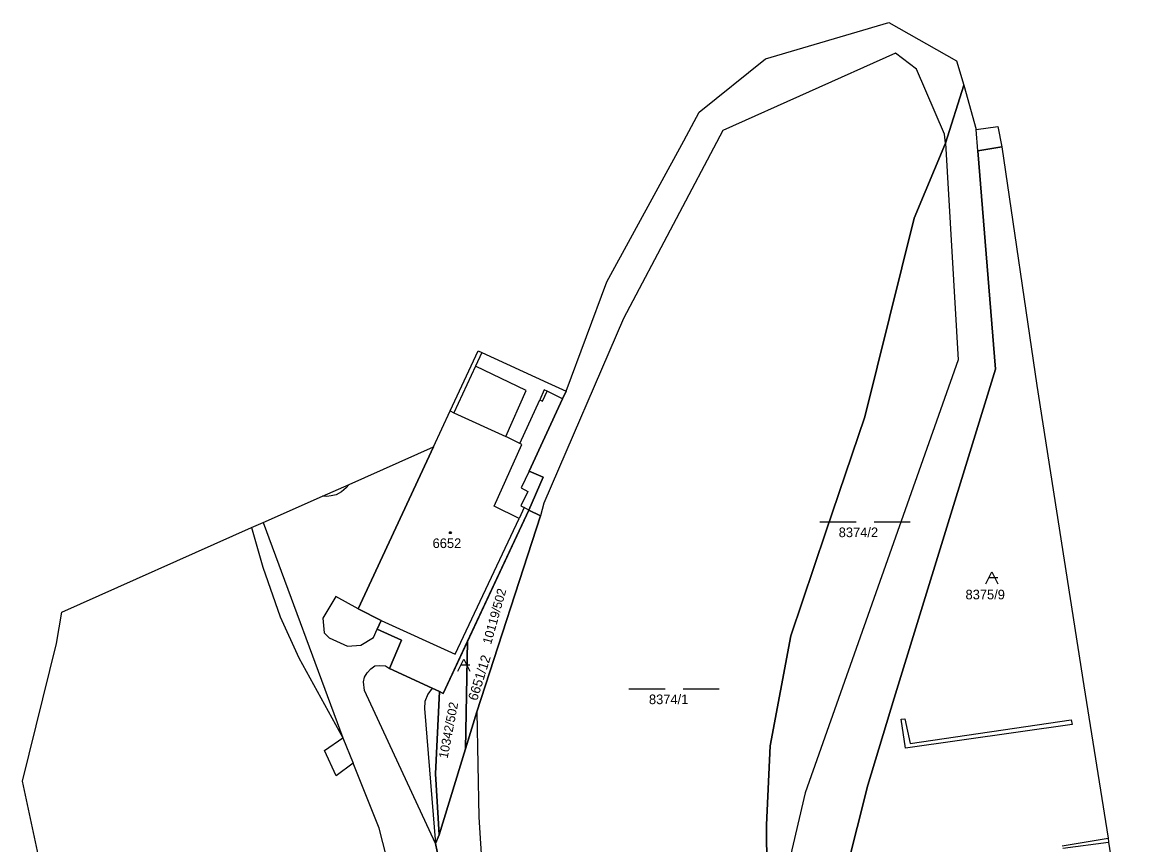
# Model space of a CAD drawing. Extents: x -263587 to -261993, y -1238795 to -1236748.
# Drawn here: x -262974.5 to -262788.7, y -1236884.7 to -1236748.1 of the extents above; entities that cross this region are included whole.
import ezdxf

# ---------------------------------------------------------------- set-up
doc = ezdxf.new("R2010")
doc.units = 0
doc.layers.add('Vrstva 1', color=7, linetype='Continuous')
doc.layers.add('Vrstva 3', color=7, linetype='Continuous')

msp = doc.modelspace()

# ---------------------------------------------------------------- linework, layer by layer
at = {"layer": 'Vrstva 1'}
for p, q in [((-262851.01, -1236754.18), (-262830.55, -1236748.12)), ((-262830.55, -1236748.12), (-262819.31, -1236754.53)), ((-262862.05, -1236763.03), (-262851.01, -1236754.18)), ((-262829.43, -1236753.23), (-262858.11, -1236766.1)), ((-262825.94, -1236755.87), (-262829.43, -1236753.23)), ((-262819.31, -1236754.53), (-262818.07, -1236758.57)), ((-262821.27, -1236766.67), (-262825.94, -1236755.87)), ((-262818.07, -1236758.57), (-262821.1, -1236768.18)), ((-262821.1, -1236768.18), (-262818.07, -1236758.57)), ((-262818.07, -1236758.57), (-262816.03, -1236765.91)), ((-262864.6, -1236767.81), (-262862.05, -1236763.03)), ((-262816.03, -1236765.91), (-262812.4, -1236765.43)), ((-262815.75, -1236769.45), (-262816.03, -1236765.91)), ((-262812.4, -1236765.43), (-262811.78, -1236768.82)), ((-262858.11, -1236766.1), (-262874.59, -1236797.31)), ((-262821.1, -1236768.18), (-262821.27, -1236766.67)), ((-262877.35, -1236791.21), (-262864.6, -1236767.81)), ((-262821.1, -1236768.18), (-262826.3, -1236780.65)), ((-262826.3, -1236780.65), (-262821.1, -1236768.18)), ((-262821.1, -1236768.18), (-262819.02, -1236804.16)), ((-262815.75, -1236769.45), (-262811.78, -1236768.82)), ((-262811.78, -1236768.82), (-262815.75, -1236769.45)), ((-262812.8, -1236805.73), (-262815.75, -1236769.45)), ((-262815.75, -1236769.45), (-262812.8, -1236805.73)), ((-262811.78, -1236768.82), (-262805.92, -1236808.45)), ((-262826.3, -1236780.65), (-262834.54, -1236813.66)), ((-262834.54, -1236813.66), (-262826.3, -1236780.65)), ((-262884.12, -1236809.37), (-262877.35, -1236791.21)), ((-262874.59, -1236797.31), (-262887.85, -1236827.96)), ((-262903.38, -1236812.67), (-262898.76, -1236802.7)), ((-262898.16, -1236802.97), (-262899.19, -1236805.24)), ((-262898.76, -1236802.7), (-262898.16, -1236802.97)), ((-262898.16, -1236802.97), (-262887.16, -1236808.02)), ((-262819.02, -1236804.16), (-262844.42, -1236876.11)), ((-262899.19, -1236805.24), (-262902.76, -1236812.99)), ((-262890.76, -1236809.26), (-262899.19, -1236805.24)), ((-262829.62, -1236860.38), (-262812.8, -1236805.73)), ((-262812.8, -1236805.73), (-262829.62, -1236860.38)), ((-262887.16, -1236808.02), (-262884.12, -1236809.37)), ((-262805.92, -1236808.45), (-262798.15, -1236858.35)), ((-262894.15, -1236816.93), (-262890.76, -1236809.26)), ((-262887.76, -1236809.15), (-262888.51, -1236810.83)), ((-262888.04, -1236811.06), (-262887.26, -1236809.37)), ((-262887.26, -1236809.37), (-262887.76, -1236809.15)), ((-262884.71, -1236810.64), (-262887.26, -1236809.37)), ((-262884.71, -1236810.64), (-262884.12, -1236809.37)), ((-262884.12, -1236809.37), (-262884.71, -1236810.64)), ((-262891.81, -1236818.06), (-262888.51, -1236810.83)), ((-262890.28, -1236822.66), (-262884.71, -1236810.64)), ((-262884.71, -1236810.64), (-262890.28, -1236822.66)), ((-262888.51, -1236810.83), (-262888.04, -1236811.06)), ((-262906.15, -1236818.64), (-262903.38, -1236812.67)), ((-262903.38, -1236812.67), (-262902.76, -1236812.99)), ((-262902.76, -1236812.99), (-262894.15, -1236816.93)), ((-262834.54, -1236813.66), (-262841.02, -1236832.73)), ((-262841.02, -1236832.73), (-262834.54, -1236813.66)), ((-262891.81, -1236818.06), (-262894.15, -1236816.93)), ((-262920.15, -1236824.86), (-262906.15, -1236818.64)), ((-262918.67, -1236845.51), (-262906.15, -1236818.64)), ((-262906.15, -1236818.64), (-262918.67, -1236845.51)), ((-262896.11, -1236828.5), (-262891.49, -1236818.25)), ((-262891.49, -1236818.25), (-262891.81, -1236818.06)), ((-262890.28, -1236822.66), (-262891.58, -1236825.45)), ((-262887.93, -1236823.67), (-262890.28, -1236822.66)), ((-262890.28, -1236822.66), (-262887.93, -1236823.67)), ((-262924.62, -1236826.84), (-262920.15, -1236824.86)), ((-262920.15, -1236824.86), (-262920.65, -1236825.45)), ((-262890.33, -1236829.14), (-262887.93, -1236823.67)), ((-262887.93, -1236823.67), (-262890.33, -1236829.14)), ((-262934.47, -1236831.2), (-262924.62, -1236826.84)), ((-262923.87, -1236826.87), (-262924.62, -1236826.84)), ((-262923.14, -1236826.75), (-262923.87, -1236826.87)), ((-262922.36, -1236826.58), (-262923.14, -1236826.75)), ((-262921.43, -1236826.12), (-262922.36, -1236826.58)), ((-262920.65, -1236825.45), (-262921.43, -1236826.12)), ((-262890.48, -1236826.03), (-262891.65, -1236828.45)), ((-262891.58, -1236825.45), (-262890.48, -1236826.03)), ((-262891.96, -1236830.52), (-262896.11, -1236828.5)), ((-262891.08, -1236828.73), (-262891.96, -1236830.52)), ((-262891.65, -1236828.45), (-262891.08, -1236828.73)), ((-262890.33, -1236829.14), (-262891.08, -1236828.73)), ((-262887.85, -1236827.96), (-262888.39, -1236830.09)), ((-262890.33, -1236829.14), (-262904.55, -1236859.58)), ((-262904.55, -1236859.58), (-262890.33, -1236829.14)), ((-262902.55, -1236853.04), (-262891.96, -1236830.52)), ((-262898.96, -1236862.63), (-262888.39, -1236830.09)), ((-262888.39, -1236830.09), (-262898.96, -1236862.63)), ((-262888.39, -1236830.09), (-262890.33, -1236829.14)), ((-262890.33, -1236829.14), (-262888.39, -1236830.09)), ((-262967.91, -1236846.08), (-262936.37, -1236832.04)), ((-262936.37, -1236832.04), (-262934.47, -1236831.2)), ((-262936.37, -1236832.04), (-262934.52, -1236838.61)), ((-262934.47, -1236831.2), (-262934.46, -1236831.22)), ((-262934.46, -1236831.22), (-262921.21, -1236866.94)), ((-262841.02, -1236832.73), (-262846.82, -1236850)), ((-262846.82, -1236850), (-262841.02, -1236832.73)), ((-262841.98, -1236831.06), (-262835.98, -1236831.06)), ((-262832.98, -1236831.06), (-262826.98, -1236831.06)), ((-262934.52, -1236838.61), (-262931.64, -1236846.84)), ((-262812.41, -1236840.39), (-262813.91, -1236840.39)), ((-262922.4, -1236843.47), (-262924.55, -1236847.09)), ((-262918.67, -1236845.51), (-262922.4, -1236843.47)), ((-262914.87, -1236847.46), (-262918.67, -1236845.51)), ((-262918.67, -1236845.51), (-262914.87, -1236847.46)), ((-262968.77, -1236851.29), (-262967.91, -1236846.08)), ((-262931.64, -1236846.84), (-262928.56, -1236853.68)), ((-262924.55, -1236847.09), (-262924.35, -1236849.55)), ((-262915.54, -1236848.94), (-262914.87, -1236847.46)), ((-262914.87, -1236847.46), (-262915.54, -1236848.94)), ((-262914.87, -1236847.46), (-262902.55, -1236853.04)), ((-262916.15, -1236850.3), (-262915.54, -1236848.94)), ((-262911.49, -1236850.73), (-262915.54, -1236848.94)), ((-262915.54, -1236848.94), (-262911.49, -1236850.73)), ((-262974.46, -1236874.15), (-262968.77, -1236851.29)), ((-262924.35, -1236849.55), (-262923.5, -1236850.38)), ((-262923.5, -1236850.38), (-262920.47, -1236851.74)), ((-262918.21, -1236851.56), (-262916.15, -1236850.3)), ((-262913.47, -1236855.44), (-262911.49, -1236850.73)), ((-262911.49, -1236850.73), (-262913.47, -1236855.44)), ((-262846.82, -1236850), (-262850.26, -1236868.31)), ((-262850.26, -1236868.31), (-262846.82, -1236850)), ((-262920.47, -1236851.74), (-262918.21, -1236851.56)), ((-262928.56, -1236853.68), (-262921.21, -1236866.94)), ((-262916.55, -1236855.52), (-262915.92, -1236855.01)), ((-262915.92, -1236855.01), (-262915.15, -1236854.95)), ((-262915.15, -1236854.95), (-262914.12, -1236855.01)), ((-262914.12, -1236855.01), (-262913.47, -1236855.44)), ((-262900.12, -1236854.89), (-262901.62, -1236854.89)), ((-262917.81, -1236857.64), (-262917.61, -1236856.9)), ((-262917.61, -1236856.9), (-262917.21, -1236856.15)), ((-262917.21, -1236856.15), (-262916.55, -1236855.52)), ((-262906.41, -1236858.72), (-262913.47, -1236855.44)), ((-262913.47, -1236855.44), (-262906.41, -1236858.72)), ((-262917.61, -1236859.1), (-262917.81, -1236857.64)), ((-262906.41, -1236858.72), (-262907.1, -1236859.72)), ((-262905.18, -1236859.29), (-262906.41, -1236858.72)), ((-262906.41, -1236858.72), (-262905.18, -1236859.29)), ((-262873.69, -1236858.8), (-262867.69, -1236858.8)), ((-262864.69, -1236858.8), (-262858.69, -1236858.8)), ((-262798.15, -1236858.35), (-262794.11, -1236883.63)), ((-262905.84, -1236884.51), (-262917.61, -1236859.1)), ((-262907.1, -1236859.72), (-262907.58, -1236860.95)), ((-262905.83, -1236872.97), (-262905.18, -1236859.29)), ((-262905.18, -1236859.29), (-262905.83, -1236872.97)), ((-262904.55, -1236859.58), (-262905.18, -1236859.29)), ((-262905.18, -1236859.29), (-262904.55, -1236859.58)), ((-262834.02, -1236874.83), (-262829.62, -1236860.38)), ((-262829.62, -1236860.38), (-262834.02, -1236874.83)), ((-262907.58, -1236860.95), (-262907.67, -1236862.09)), ((-262907.67, -1236862.09), (-262905.84, -1236884.51)), ((-262905.25, -1236883.1), (-262898.96, -1236862.63)), ((-262898.96, -1236862.63), (-262905.25, -1236883.1)), ((-262898.96, -1236862.63), (-262898.62, -1236880.12)), ((-262828.49, -1236863.87), (-262827.85, -1236863.8)), ((-262827.76, -1236868.7), (-262828.49, -1236863.87)), ((-262827.85, -1236863.8), (-262826.99, -1236867.9)), ((-262826.99, -1236867.9), (-262800.24, -1236863.96)), ((-262800.24, -1236863.96), (-262800.08, -1236864.73)), ((-262800.08, -1236864.73), (-262827.76, -1236868.7)), ((-262924.28, -1236869.09), (-262921.21, -1236866.94)), ((-262921.21, -1236866.94), (-262919.52, -1236871.17)), ((-262922.36, -1236873.29), (-262924.28, -1236869.09)), ((-262850.26, -1236868.31), (-262850.84, -1236881.41)), ((-262850.84, -1236881.41), (-262850.26, -1236868.31)), ((-262919.52, -1236871.17), (-262922.36, -1236873.29)), ((-262915.21, -1236881.98), (-262919.52, -1236871.17)), ((-262905.25, -1236883.1), (-262905.83, -1236872.97)), ((-262905.83, -1236872.97), (-262905.25, -1236883.1)), ((-262968.94, -1236899.65), (-262974.46, -1236874.15)), ((-262839.47, -1236896.52), (-262834.02, -1236874.83)), ((-262834.02, -1236874.83), (-262839.47, -1236896.52)), ((-262844.42, -1236876.11), (-262850.39, -1236901.33)), ((-262898.62, -1236880.12), (-262896.26, -1236919.78)), ((-262912.04, -1236894.28), (-262915.21, -1236881.98)), ((-262850.84, -1236881.41), (-262850.76, -1236891.53)), ((-262850.76, -1236891.53), (-262850.84, -1236881.41)), ((-262905.84, -1236884.51), (-262905.25, -1236883.1)), ((-262905.25, -1236883.1), (-262905.84, -1236884.51)), ((-262904.99, -1236888.5), (-262905.84, -1236884.51)), ((-262905.84, -1236884.51), (-262904.99, -1236888.5)), ((-262801.72, -1236884.9), (-262794.11, -1236883.63)), ((-262801.64, -1236885.31), (-262794.02, -1236884.29)), ((-262794.11, -1236883.63), (-262794.02, -1236884.29)), ((-262794.02, -1236884.29), (-262788.7, -1236918.04))]:
    msp.add_line(p, q, dxfattribs=at)
msp.add_lwpolyline([(-262903.27, -1236832.72), (-262903.18, -1236832.87), (-262903.27, -1236833.02), (-262903.45, -1236833.02), (-262903.54, -1236832.87), (-262903.45, -1236832.72)], close=True, dxfattribs=at)
for points in [[(-262814.41, -1236841.39), (-262813.41, -1236839.39), (-262812.41, -1236841.39)], [(-262902.12, -1236855.89), (-262901.12, -1236853.89), (-262900.12, -1236855.89)]]:
    msp.add_lwpolyline(points, dxfattribs=at)
at = {"layer": 'Vrstva 3'}
for points in [[(-262905.25, -1236883.1), (-262900.86, -1236868.814), (-262898.96, -1236862.63), (-262888.39, -1236830.09), (-262890.33, -1236829.14), (-262900.5, -1236850.911), (-262904.55, -1236859.58), (-262905.18, -1236859.29), (-262905.83, -1236872.97)], [(-262900.86, -1236868.814), (-262900.5, -1236850.911), (-262890.33, -1236829.14), (-262888.39, -1236830.09), (-262898.96, -1236862.63)], [(-262900.5, -1236850.911), (-262900.86, -1236868.814), (-262905.25, -1236883.1), (-262905.83, -1236872.97), (-262905.18, -1236859.29), (-262904.55, -1236859.58)]]:
    msp.add_lwpolyline(points, close=True, dxfattribs=at)

# ---------------------------------------------------------------- texts
at = {"layer": 'Vrstva 1'}
for s, p in [('8374/2', (-262838.853, -1236833.63)), ('6652', (-262906.316, -1236835.44)), ('8375/9', (-262817.789, -1236843.96)), ('8374/1', (-262870.374, -1236861.37))]:
    msp.add_text(s, height=1.6, dxfattribs=at).set_placement(p)
msp.add_text('6651/12', height=1.6, rotation=72.65105, dxfattribs=at).set_placement((-262898.929, -1236860.907))
at = {"layer": 'Vrstva 3'}
for s, rotation, p in [('10119/502', 74.36992, (-262896.6, -1236851.543)), ('10342/502', 79.12547, (-262903.835, -1236870.497))]:
    msp.add_text(s, height=1.5, rotation=rotation, dxfattribs=at).set_placement(p)

doc.saveas('drawing.dxf')
